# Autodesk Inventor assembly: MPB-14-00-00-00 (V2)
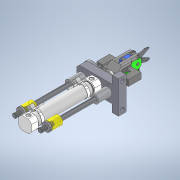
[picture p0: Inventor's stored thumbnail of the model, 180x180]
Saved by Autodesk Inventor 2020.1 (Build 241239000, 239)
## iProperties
Created: 2020-04
Part Number: MPB-14-00-00-00 (V2)
Document SubType Name: Assembly
Designer: Safarabadi
Author: Safarabadi
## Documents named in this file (19)
- C:\Users\Safarabadi\Desktop\00-GrabCAD\00-Mask\MPB (75) - Face mask ear loop welding machine - (3D & 2D)\MPB-14-00-00-00 (V2)\MPB-14-00-00-00 (V2).iam
- C:\Users\Safarabadi\Desktop\00-GrabCAD\00-Mask\MPB (75) - Face mask ear loop welding machine - (3D & 2D)\MPB-14-00-00-00 (V2)\MPB-14-01-00-00 (V2).ipt
- C:\Users\Safarabadi\Desktop\00-GrabCAD\00-Mask\MPB (75) - Face mask ear loop welding machine - (3D & 2D)\MPB-14-00-00-00 (V2)\MPB-14-02-00-00 (V2).ipt
- C:\Users\Safarabadi\Desktop\00-GrabCAD\00-Mask\MPB (75) - Face mask ear loop welding machine - (3D & 2D)\MPB-14-00-00-00 (V2)\MPB-14-03-00-00 (V2).ipt
- C:\Users\Safarabadi\Desktop\00-GrabCAD\00-Mask\MPB (75) - Face mask ear loop welding machine - (3D & 2D)\MPB-14-00-00-00 (V2)\MPB-14-04-00-00 (V2).ipt
- C:\Users\Safarabadi\Desktop\00-GrabCAD\00-Mask\MPB (75) - Face mask ear loop welding machine - (3D & 2D)\MPB-14-00-00-00 (V2)\MPB-14-05-00-00 (V2).ipt
- C:\Users\Safarabadi\Desktop\00-GrabCAD\00-Mask\MPB (75) - Face mask ear loop welding machine - (3D & 2D)\MPB-14-00-00-00 (V2)\MPB-14-06-00-00 (V2).ipt
- C:\Users\Safarabadi\Desktop\00-GrabCAD\00-Mask\MPB (75) - Face mask ear loop welding machine - (3D & 2D)\MPB-14-00-00-00 (V2)\MPB-14-07-00-00 (V2).ipt
- C:\Users\Safarabadi\Desktop\00-GrabCAD\00-Mask\MPB (75) - Face mask ear loop welding machine - (3D & 2D)\MPB-14-00-00-00 (V2)\MPB-14-08-00-00 (V2).ipt
- C:\Users\Safarabadi\Desktop\00-GrabCAD\00-Mask\MPB (75) - Face mask ear loop welding machine - (3D & 2D)\MPB-14-00-00-00 (V2)\MPB-14-09-00-00 (V2).ipt
- C:\Users\Safarabadi\Desktop\00-GrabCAD\00-Mask\MPB (75) - Face mask ear loop welding machine - (3D & 2D)\MPB-14-00-00-00 (V2)\MPB-14-10-00-00 (V2).ipt
- C:\Users\Safarabadi\Desktop\00-GrabCAD\00-Mask\MPB (75) - Face mask ear loop welding machine - (3D & 2D)\MPB-14-00-00-00 (V2)\MI25x100SU(0)+(CMSG-1)\MI25x100SU(0)+(CMSG-1).iam
- C:\Users\Safarabadi\Desktop\00-GrabCAD\00-Mask\MPB (75) - Face mask ear loop welding machine - (3D & 2D)\MPB-14-00-00-00 (V2)\LMH10LUU.ipt
- C:\Users\Safarabadi\Desktop\00-GrabCAD\00-Mask\MPB (75) - Face mask ear loop welding machine - (3D & 2D)\MPB-14-00-00-00 (V2)\Clevis pin - B - 4 x 24DIN EN.ipt
- C:\Users\Safarabadi\Desktop\00-GrabCAD\00-Mask\MPB (75) - Face mask ear loop welding machine - (3D & 2D)\MPB-14-00-00-00 (V2)\Split Pin - 1 x 8.ipt
- C:\Users\Safarabadi\Desktop\00-GrabCAD\00-Mask\MPB (75) - Face mask ear loop welding machine - (3D & 2D)\MPB-14-00-00-00 (V2)\Conical Spring Washer - 4.ipt
- C:\Users\Safarabadi\Desktop\00-GrabCAD\00-Mask\MPB (75) - Face mask ear loop welding machine - (3D & 2D)\MPB-14-00-00-00 (V2)\ISO 2341 - A - 5 x 35DIN EN.ipt
- C:\Users\Safarabadi\Desktop\00-GrabCAD\00-Mask\MPB (75) - Face mask ear loop welding machine - (3D & 2D)\MPB-14-00-00-00 (V2)\ISO 8752 - 2 x 10  (1) DIN EN ISO.ipt
- C:\Users\Safarabadi\Desktop\00-GrabCAD\00-Mask\MPB (75) - Face mask ear loop welding machine - (3D & 2D)\MPB-14-00-00-00 (V2)\Compress Spring11.ipt
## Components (31 placed, 18 different names)
1. MPB-14-01-00-00 (V2):1 — 105, Insert:1, Mate:1, Insert:2, Mate:2, Insert:5, Angle:1
2. MPB-14-02-00-00 (V2):1 — 105, M2, Insert:6, Flush:1, Insert:15, Insert:16
3. MPB-14-03-00-00 (V2):1 — Insert:3, Insert:4, Flush:1, Flush:2, Flush:3, Mate:5, M2, Insert:21, Mate:22, Flush:6, Mate:23, Mate:24, Flush:7, Mate:25
4. MPB-14-04-00-00 (V2):1 — Flush:2, Flush:3, Mate:5, Flush:4, Mate:6, Mate:7, Mate:9, Insert:20
5. MPB-14-05-00-00 (V2):1 — Flush:4, Mate:6, Mate:7, Mate:8, Flush:5, Insert:7, Insert:17
6. MPB-14-05-00-00 (V2):2 — Mate:8, Flush:5, Mate:9, Insert:8, Insert:18
7. MPB-14-06-00-00 (V2):1 — Insert:7, Insert:9
8. MPB-14-06-00-00 (V2):2 — Insert:8, Insert:10
9. MPB-14-07-00-00 (V2):1 — Insert:9, Mate:21
10. MPB-14-07-00-00 (V2):2 — Insert:10, Mate:20
11. MPB-14-08-00-00 (V2):1 — Insert:3, Mate:3, Insert:11
12. MPB-14-08-00-00 (V2):2 — Insert:4, Mate:4, Insert:12
13. MPB-14-09-00-00 (V2):1 — Insert:11, Insert:13
14. MPB-14-09-00-00 (V2):2 — Insert:12, Insert:14
15. MPB-14-10-00-00 (V2):1 — Insert:13
16. MPB-14-10-00-00 (V2):2 — Insert:14
17. MI25x100SU(0)+(CMSG-1):1 [sub-assembly] — Insert:5, Angle:1, Insert:6
18. LMH10LUU:1 — Insert:1, Mate:1, Mate:3
19. LMH10LUU:2 — Insert:2, Mate:2, Mate:4
20. Clevis pin - B - 4 x 24DIN EN:1 — Insert:15, Mate:11, Mate:12, Mate:13, Mate:20
21. Clevis pin - B - 4 x 24DIN EN:2 — Insert:16, Mate:14, Mate:15, Mate:16, Mate:21
22. Split Pin - 1 x 8:1 — Mate:11, Mate:12, Mate:13
23. Split Pin - 1 x 8:2 — Mate:14, Mate:15, Mate:16
24. Clevis pin - B - 4 x 24DIN EN:3 — Insert:17, Mate:17, Mate:18, Mate:19
25. Conical Spring Washer - 4:1 — Insert:18, Insert:19
26. Conical Spring Washer - 4:2 — Insert:19
27. Split Pin - 1 x 8:3 — Mate:17, Mate:18, Mate:19
28. ISO 2341 - A - 5 x 35DIN EN:1 — Insert:20
29. ISO 8752 - 2 x 10  (1) DIN EN ISO:1 — Insert:21
30. Compress Spring1:1 — Mate:22, Flush:6, Mate:23
31. Compress Spring1:2 — Mate:24, Flush:7, Mate:25
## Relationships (55: Mate 26, Insert 21, Flush 7, Angle 1)
- 105 [Mate]: MPB-14-01-00-00 (V2):1 ↔ MPB-14-02-00-00 (V2):1
- M2 [Mate]: MPB-14-02-00-00 (V2):1 ↔ MPB-14-03-00-00 (V2):1
- Insert:1: MPB-14-01-00-00 (V2):1 ↔ LMH10LUU:1
- Mate:1: MPB-14-01-00-00 (V2):1 ↔ LMH10LUU:1
- Insert:2: MPB-14-01-00-00 (V2):1 ↔ LMH10LUU:2
- Mate:2: MPB-14-01-00-00 (V2):1 ↔ LMH10LUU:2
- Insert:3: MPB-14-03-00-00 (V2):1 ↔ MPB-14-08-00-00 (V2):1
- Insert:4: MPB-14-03-00-00 (V2):1 ↔ MPB-14-08-00-00 (V2):2
- Insert:5: MPB-14-01-00-00 (V2):1 ↔ MI25x100SU(0)+(CMSG-1):1
- Angle:1: MPB-14-01-00-00 (V2):1 ↔ MI25x100SU(0)+(CMSG-1):1
- Insert:6: MPB-14-02-00-00 (V2):1 ↔ MI25x100SU(0)+(CMSG-1):1
- Mate:3: MPB-14-08-00-00 (V2):1 ↔ LMH10LUU:1
- Mate:4: MPB-14-08-00-00 (V2):2 ↔ LMH10LUU:2
- Flush:1: MPB-14-02-00-00 (V2):1 ↔ MPB-14-03-00-00 (V2):1
- Flush:2: MPB-14-03-00-00 (V2):1 ↔ MPB-14-04-00-00 (V2):1
- Flush:3: MPB-14-03-00-00 (V2):1 ↔ MPB-14-04-00-00 (V2):1
- Mate:5: MPB-14-03-00-00 (V2):1 ↔ MPB-14-04-00-00 (V2):1
- Flush:4: MPB-14-04-00-00 (V2):1 ↔ MPB-14-05-00-00 (V2):1
- Mate:6: MPB-14-04-00-00 (V2):1 ↔ MPB-14-05-00-00 (V2):1
- Mate:7: MPB-14-04-00-00 (V2):1 ↔ MPB-14-05-00-00 (V2):1
- Mate:8: MPB-14-05-00-00 (V2):1 ↔ MPB-14-05-00-00 (V2):2
- Flush:5: MPB-14-05-00-00 (V2):1 ↔ MPB-14-05-00-00 (V2):2
- Mate:9: MPB-14-04-00-00 (V2):1 ↔ MPB-14-05-00-00 (V2):2
- Insert:7: MPB-14-05-00-00 (V2):1 ↔ MPB-14-06-00-00 (V2):1
- Insert:8: MPB-14-05-00-00 (V2):2 ↔ MPB-14-06-00-00 (V2):2
- Insert:9: MPB-14-06-00-00 (V2):1 ↔ MPB-14-07-00-00 (V2):1
- Insert:10: MPB-14-06-00-00 (V2):2 ↔ MPB-14-07-00-00 (V2):2
- Insert:11: MPB-14-08-00-00 (V2):1 ↔ MPB-14-09-00-00 (V2):1
- Insert:12: MPB-14-08-00-00 (V2):2 ↔ MPB-14-09-00-00 (V2):2
- Insert:13: MPB-14-09-00-00 (V2):1 ↔ MPB-14-10-00-00 (V2):1
- Insert:14: MPB-14-09-00-00 (V2):2 ↔ MPB-14-10-00-00 (V2):2
- Insert:15: MPB-14-02-00-00 (V2):1 ↔ Clevis pin - B - 4 x 24DIN EN:1
- Insert:16: MPB-14-02-00-00 (V2):1 ↔ Clevis pin - B - 4 x 24DIN EN:2
- Mate:11: Clevis pin - B - 4 x 24DIN EN:1 ↔ Split Pin - 1 x 8:1
- Mate:12: Clevis pin - B - 4 x 24DIN EN:1 ↔ Split Pin - 1 x 8:1
- Mate:13: Clevis pin - B - 4 x 24DIN EN:1 ↔ Split Pin - 1 x 8:1
- Mate:14: Clevis pin - B - 4 x 24DIN EN:2 ↔ Split Pin - 1 x 8:2
- Mate:15: Clevis pin - B - 4 x 24DIN EN:2 ↔ Split Pin - 1 x 8:2
- Mate:16: Clevis pin - B - 4 x 24DIN EN:2 ↔ Split Pin - 1 x 8:2
- Insert:17: MPB-14-05-00-00 (V2):1 ↔ Clevis pin - B - 4 x 24DIN EN:3
- Insert:18: MPB-14-05-00-00 (V2):2 ↔ Conical Spring Washer - 4:1
- Insert:19: Conical Spring Washer - 4:1 ↔ Conical Spring Washer - 4:2
- Mate:17: Clevis pin - B - 4 x 24DIN EN:3 ↔ Split Pin - 1 x 8:3
- Mate:18: Clevis pin - B - 4 x 24DIN EN:3 ↔ Split Pin - 1 x 8:3
- Mate:19: Clevis pin - B - 4 x 24DIN EN:3 ↔ Split Pin - 1 x 8:3
- Mate:20: MPB-14-07-00-00 (V2):2 ↔ Clevis pin - B - 4 x 24DIN EN:1
- Mate:21: MPB-14-07-00-00 (V2):1 ↔ Clevis pin - B - 4 x 24DIN EN:2
- Insert:20: MPB-14-04-00-00 (V2):1 ↔ ISO 2341 - A - 5 x 35DIN EN:1
- Insert:21: MPB-14-03-00-00 (V2):1 ↔ ISO 8752 - 2 x 10  (1) DIN EN ISO:1
- Mate:22: MPB-14-03-00-00 (V2):1 ↔ Compress Spring1:1
- Flush:6: MPB-14-03-00-00 (V2):1 ↔ Compress Spring1:1
- Mate:23: MPB-14-03-00-00 (V2):1 ↔ Compress Spring1:1
- Mate:24: MPB-14-03-00-00 (V2):1 ↔ Compress Spring1:2
- Flush:7: MPB-14-03-00-00 (V2):1 ↔ Compress Spring1:2
- Mate:25: MPB-14-03-00-00 (V2):1 ↔ Compress Spring1:2
